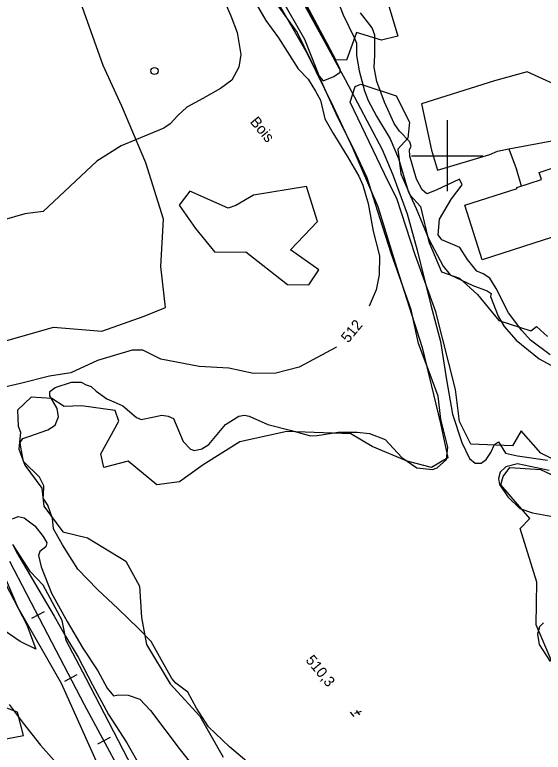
# Model space of a CAD drawing. Extents: x 347312 to 350503, y 6073086 to 6076432.
# Drawn here: x 348178.2 to 348327.1, y 6074432 to 6074639.7 of the extents above; entities that cross this region are included whole.
import ezdxf

# ---------------------------------------------------------------- set-up
doc = ezdxf.new("R2010")
doc.units = 0
for name, color, linetype in [('Level 1', 7, 'Continuous'), ('Level 19', 7, 'Continuous'), ('Level 2', 7, 'Continuous'), ('Level 21', 7, 'Continuous'), ('Level 23', 7, 'Continuous'), ('Level 3', 7, 'Continuous'), ('Level 31', 7, 'Continuous'), ('Level 36', 7, 'Continuous'), ('Level 4', 7, 'Continuous'), ('Level 44', 7, 'Continuous'), ('Level 61', 7, 'Continuous')]:
    doc.layers.add(name, color=color, linetype=linetype)

msp = doc.modelspace()

# ---------------------------------------------------------------- linework, layer by layer
at = {"layer": 'Level 1'}
msp.add_lwpolyline([(348252.29, 6074642.25), (348257.76, 6074634.67), (348263.48, 6074623), (348265.07, 6074621.13), (348268.09, 6074622.35), (348269.83, 6074623.57), (348269.9, 6074624.43), (348266.07, 6074631.8), (348259.68, 6074643.16)], dxfattribs=at)
at = {"layer": 'Level 19'}
msp.add_lwpolyline([(348317.36, 6074601.94), (348319.4, 6074596.44), (348320.88, 6074591.5)], dxfattribs=at)
at = {"layer": 'Level 2'}
for points in [[(348233.28, 6074652.95), (348239.12, 6074639.42), (348240.83, 6074634.71), (348241.92, 6074628.53), (348241.34, 6074624.96), (348239.38, 6074621.28), (348236.16, 6074618.94)], [(348241.81, 6074650.48), (348248.98, 6074638.06), (348252.5, 6074633.26), (348258.01, 6074624.53), (348260.88, 6074621.6), (348262.92, 6074618.24), (348264.31, 6074615.66), (348265.54, 6074610.4), (348267.83, 6074606.44), (348271.86, 6074599.93), (348275.16, 6074594.28), (348276.25, 6074591.72), (348277.79, 6074586.59), (348279.18, 6074578.78), (348280.94, 6074571.8), (348280.87, 6074566.51), (348280.02, 6074562.29), (348277.99, 6074557.7)], [(348268.81, 6074644.6), (348270.73, 6074639.65), (348273.83, 6074633.3), (348274.5, 6074631.72), (348274.5, 6074628.23), (348275.24, 6074623.89), (348276.74, 6074618.32), (348277.74, 6074615.55), (348280.14, 6074611.14), (348283.96, 6074604.73), (348286.33, 6074599.23), (348288.99, 6074590.08), (348291.27, 6074585.18), (348291.27, 6074585.18), (348294.87, 6074576.53), (348298.85, 6074568.88), (348300.89, 6074566.52), (348302.22, 6074565.82), (348307.26, 6074563.48), (348311.22, 6074561.97), (348312.35, 6074561.25), (348312.18, 6074560.37), (348314.34, 6074554.88), (348316.05, 6074551.9), (348319.43, 6074548.07), (348325.87, 6074542.81), (348331.28, 6074539.9)], [(348329, 6074543.95), (348323.5, 6074548.11), (348321.05, 6074550.85), (348317.26, 6074555.8), (348313.77, 6074562.61), (348312.06, 6074565.58), (348310.13, 6074566.76), (348308.39, 6074567.55), (348305.77, 6074570.78), (348303.58, 6074574.13), (348298.51, 6074576.3), (348297.44, 6074577.76), (348297.85, 6074582.16), (348301.26, 6074587.86), (348304.2, 6074591.86), (348303.46, 6074593.38), (348296.92, 6074590.33), (348294.28, 6074589.33), (348292.92, 6074590.41), (348291.35, 6074593.39), (348291.35, 6074593.39), (348289.49, 6074599.85), (348289.35, 6074601.75), (348289.85, 6074602.58), (348289.53, 6074603.91), (348286.59, 6074606.91), (348285.04, 6074609.07), (348282.35, 6074615.09), (348280.22, 6074620.92), (348279.45, 6074624.82), (348279.59, 6074628.29), (348279.61, 6074633.93), (348278.91, 6074636.02), (348275.64, 6074640.21)], [(348236.16, 6074618.94), (348231.23, 6074616.09), (348226.7, 6074613.71), (348224.13, 6074611.38), (348221.99, 6074609.02), (348220.23, 6074607.79), (348208.17, 6074602.83), (348201.31, 6074598.46), (348186.26, 6074584.29), (348181.05, 6074583.7), (348174.57, 6074581.76)], [(348217.52, 6074543.71), (348214.32, 6074545.28), (348211.27, 6074545.24), (348201.55, 6074542.34), (348194.02, 6074538.89), (348188, 6074537.93), (348179.86, 6074535.84), (348174.11, 6074534.57), (348169.66, 6074533.34), (348168.63, 6074532.33)], [(348268.88, 6074546.23), (348268.66, 6074546.02), (348258.37, 6074540.48), (348251.79, 6074538.77), (348245.42, 6074538.71), (348238.52, 6074540.23), (348230.16, 6074540.63), (348219.4, 6074542.75), (348217.52, 6074543.71)], [(348177.63, 6074497.76), (348179.21, 6074498.43), (348180.84, 6074498.08), (348183.85, 6074495.79), (348186.22, 6074492.83), (348187.23, 6074491), (348186.99, 6074489.86), (348185.29, 6074488.54), (348184.9, 6074487.41), (348185.67, 6074484.29), (348188.61, 6074476.85), (348193.04, 6074468.91), (348197.42, 6074461.35), (348201.62, 6074454.96), (348204.26, 6074450.09), (348206.05, 6074447.98), (348207.45, 6074448.23), (348210.19, 6074448.15), (348213.43, 6074447.01), (348216.43, 6074443.78), (348224.81, 6074432.76), (348232.1, 6074423.5)], [(348177.95, 6074489.93), (348178.69, 6074488.41), (348184.98, 6074477.65), (348189.31, 6074470.32), (348192.57, 6074464.78)], [(348174.35, 6074481.97), (348181.59, 6074467.9), (348184.15, 6074461.04), (348179.77, 6074463.24), (348167.05, 6074471.84)], [(348192.57, 6074464.78), (348196.11, 6074458.79), (348200.11, 6074451.05), (348204.65, 6074442.68), (348209.79, 6074434.7), (348215.8, 6074424.1)], [(348176.65, 6074445.45), (348180.64, 6074440.26), (348185.48, 6074434.06), (348197, 6074421.07)]]:
    msp.add_lwpolyline(points, dxfattribs=at)
at = {"layer": 'Level 21'}
msp.add_lwpolyline([(348355.35, 6074625.06), (348349.83, 6074623.31), (348339.45, 6074620.82), (348336.86, 6074619.53), (348331.15, 6074619.73), (348322.5, 6074623.62), (348313.34, 6074621.1), (348292.78, 6074614.64), (348295.6, 6074601.54), (348297.29, 6074595.91), (348312.03, 6074600.37), (348314.14, 6074601.34), (348317.36, 6074601.94), (348335.05, 6074605.26), (348339.96, 6074606.18), (348355.07, 6074611.84), (348359.78, 6074613.61), (348362.29, 6074614.55)], dxfattribs=at)
at = {"layer": 'Level 23'}
for p, q in [((348186.48, 6074471.61), (348182.94, 6074469.74)), ((348195.74, 6074453.88), (348192.21, 6074452.01)), ((348205.11, 6074436.21), (348201.57, 6074434.35))]:
    msp.add_line(p, q, dxfattribs=at)
msp.add_lwpolyline([(348326.4, 6074201.06), (348311.81, 6074229.17), (348300.87, 6074250.44), (348298.17, 6074255.91), (348281.64, 6074286.79), (348280.07, 6074289.79), (348271.75, 6074305.66), (348261.22, 6074325.38), (348248.86, 6074348.82), (348238.93, 6074367.57), (348229.17, 6074386.4), (348218.8, 6074405.95), (348208.19, 6074426.24), (348197.9, 6074445.44), (348186.42, 6074467.4), (348176.81, 6074485.77)], dxfattribs=at)
at = {"layer": 'Level 3'}
for p, q in [((348275.77, 6074443.53), (348273.94, 6074442.98)), ((348274.35, 6074443.84), (348275.34, 6074442.63)), ((348272.67, 6074443.36), (348273.69, 6074442.12))]:
    msp.add_line(p, q, dxfattribs=at)
at = {"layer": 'Level 31'}
msp.add_lwpolyline([(348327, 6074576.21), (348309.85, 6074570.74), (348304.96, 6074586.08), (348319.72, 6074590.79), (348319.62, 6074591.1), (348326.59, 6074593.32), (348325.95, 6074595.33), (348329.31, 6074596.4), (348330.02, 6074594.17), (348337.26, 6074596.48), (348340.37, 6074586.74), (348333.45, 6074584.53), (348335.26, 6074578.85), (348327, 6074576.21)], dxfattribs=at)
at = {"layer": 'Level 36'}
msp.add_circle((348217.59, 6074623.88), 1, dxfattribs=at)
at = {"layer": 'Level 4'}
for points in [[(348299.85, 6074514.47), (348299.85, 6074514.47), (348300.17, 6074517.97), (348298.26, 6074525.85), (348297.49, 6074532.28), (348295.25, 6074538.39), (348291.95, 6074547.16), (348289.9, 6074556.66), (348284.21, 6074572.61), (348280.47, 6074584.32), (348277.47, 6074593.79), (348273.83, 6074601.67), (348269.24, 6074610.78), (348264.55, 6074621.1), (348259.9, 6074632.73), (348253.28, 6074644.46)], [(348258.95, 6074643.98), (348265.02, 6074633), (348271.28, 6074621.52), (348281.68, 6074601.73), (348284.73, 6074594.64), (348288.78, 6074583.64), (348291.59, 6074573.42), (348295.4, 6074557.93), (348298.08, 6074547.75), (348299.84, 6074536.87), (348301.51, 6074527.28), (348304.11, 6074519.29), (348306.32, 6074514.74), (348307.93, 6074513.44), (348309.53, 6074513.42), (348310.98, 6074514.48), (348312.27, 6074516.45), (348313.3, 6074518.74)], [(348196.02, 6074483.59), (348191.68, 6074490.43), (348189.13, 6074494.93), (348188.83, 6074497.91), (348187.56, 6074501.59), (348186.27, 6074503.6), (348186.31, 6074504.54), (348186.38, 6074507.07), (348185.2, 6074509.48), (348180.72, 6074513.95), (348180.05, 6074517.37), (348179.77, 6074519.24), (348180.49, 6074520.37), (348182.23, 6074520.99), (348187.56, 6074522.8), (348189.61, 6074524.13), (348190.57, 6074526.5), (348190.17, 6074528.87), (348188.07, 6074532.39), (348188.1, 6074533.61), (348189.64, 6074534.75), (348194.2, 6074536.22), (348196.96, 6074536.25), (348198.37, 6074535.55), (348199.72, 6074535.01), (348201.16, 6074533.73), (348204.21, 6074531.53), (348206.18, 6074530.69), (348208.67, 6074529.6), (348212.52, 6074526.34), (348213.82, 6074525.77), (348217.46, 6074526.46), (348219.63, 6074526.92), (348221.42, 6074526.68), (348222.96, 6074526), (348225.7, 6074519.56), (348227.75, 6074517.36), (348228.83, 6074517.06), (348230.89, 6074517.48), (348232.85, 6074518.74), (348237.62, 6074524.29), (348241.29, 6074526.67), (348242.92, 6074526.97), (348244.29, 6074526.68), (348249.54, 6074524.35), (348255.76, 6074522.76), (348261.53, 6074521.17), (348263.42, 6074521.24), (348269.29, 6074522.14), (348274.63, 6074522.14), (348278.17, 6074521.78), (348282.54, 6074520.07), (348287.22, 6074515.09), (348291.5, 6074512.11), (348295.86, 6074511.67), (348297.21, 6074512.12), (348299.85, 6074514.47)], [(348313.3, 6074518.74), (348314.47, 6074519.41), (348316.44, 6074516.23), (348319.79, 6074515.56), (348328.22, 6074514.3)], [(348328.76, 6074511.42), (348319.81, 6074513.23), (348316.56, 6074512.41), (348314.9, 6074510.94), (348314.42, 6074509.16), (348314.73, 6074507.43), (348317.13, 6074503.93), (348320.49, 6074500.64), (348323.99, 6074499.44), (348329.21, 6074498.55)], [(348243.6, 6074429.41), (348238.68, 6074433.59), (348232.82, 6074439.17), (348229.4, 6074444.45), (348226.98, 6074448.98), (348223.56, 6074451.54), (348222.49, 6074452.83), (348219.03, 6074458.97), (348216.62, 6074463.21), (348213.05, 6074466.86), (348207.36, 6074472.43), (348201.5, 6074477.92), (348196.02, 6074483.59)], [(348327.13, 6074468.5), (348326.01, 6074467.4), (348325.46, 6074465.34), (348325.91, 6074462.35), (348329.03, 6074457.63)]]:
    msp.add_lwpolyline(points, dxfattribs=at)
at = {"layer": 'Level 44'}
for points in [[(348173.02, 6074547.17), (348189.16, 6074551.74), (348202.73, 6074550.59), (348214.66, 6074554.82), (348220.7, 6074557.29), (348219.38, 6074568.79), (348220.1, 6074582.14), (348215.16, 6074597.97), (348208.43, 6074613.95), (348203.09, 6074625.39), (348195.36, 6074647.43)], [(348281.7, 6074648.52), (348286.15, 6074633.64), (348281.47, 6074632.59), (348274.46, 6074634.7), (348271.62, 6074626.94), (348268.68, 6074627.04), (348260.47, 6074642.33)], [(348251.85, 6074644.13), (348260.56, 6074628.84), (348267.92, 6074613.88), (348273.44, 6074602.03), (348280.48, 6074585.73), (348285.7, 6074568.63), (348292.93, 6074546.06), (348298.12, 6074524.66), (348300.21, 6074514.99), (348295.6, 6074512.21), (348288.71, 6074513.99), (348278.91, 6074518.17), (348272.83, 6074521.67), (348254.83, 6074522.33), (348241.6, 6074519.44), (348231.33, 6074513), (348224.66, 6074508.2), (348218.27, 6074507.39), (348210.17, 6074514.03), (348203.28, 6074512.2), (348202.48, 6074516.05), (348207.59, 6074525.26), (348206.55, 6074528.3), (348197.07, 6074529.58), (348192.12, 6074529.37), (348188.72, 6074531.65), (348182.85, 6074532.02), (348178.99, 6074528.36), (348179.24, 6074523.91), (348179.9, 6074522.22), (348179.39, 6074517.43), (348181.1, 6074512.84), (348185.85, 6074506.43), (348186.46, 6074501.37), (348191.78, 6074494.08), (348198.69, 6074492.46), (348209.5, 6074485.82), (348213.37, 6074478.82), (348213.97, 6074469.99), (348215.33, 6074462.41), (348222.03, 6074451.3), (348230.39, 6074442.18), (348236.97, 6074430.67)], [(348335.83, 6074511.45), (348326.39, 6074516.22), (348320.8, 6074522.54), (348318.38, 6074518.36), (348306.67, 6074518.77), (348303.44, 6074525.14), (348302.35, 6074534.22), (348296.81, 6074556.05), (348291.03, 6074572.11), (348285.82, 6074587.97), (348283.34, 6074592.75), (348277.01, 6074606.12), (348272.66, 6074615.12), (348274.12, 6074619.5), (348275.66, 6074620.18), (348285.61, 6074616.89), (348289.43, 6074609.43), (348288.94, 6074604.98), (348286.12, 6074601.88), (348286.97, 6074594.92), (348289.54, 6074588.95), (348292.52, 6074585.73), (348294.81, 6074575.78), (348298.39, 6074567.34), (348303.48, 6074565.57), (348308.55, 6074560.93), (348314.53, 6074553.58), (348323.53, 6074550.7), (348325.2, 6074551.94), (348328.29, 6074549.13)], [(348234.56, 6074572.82), (348243.26, 6074573), (348255.03, 6074563.74), (348261.09, 6074563.68), (348263.86, 6074567.93), (348255.92, 6074573.49), (348263.53, 6074581.47), (348260.41, 6074591.33), (348245.45, 6074588.93), (348240.52, 6074586.03), (348238.31, 6074585.25), (348227.53, 6074590.08), (348224.55, 6074586.09), (348229.11, 6074579.54), (348234.56, 6074572.82)], [(348329.47, 6074457.62), (348325.06, 6074467.97), (348325.23, 6074479.9), (348320.56, 6074495.09), (348323.27, 6074497.83), (348315.14, 6074507.37), (348315.75, 6074509.72), (348317.61, 6074512.21), (348326.25, 6074511.66), (348335.72, 6074507.23)], [(348169.34, 6074495.52), (348178.98, 6074473.02), (348191.32, 6074451.52), (348201.55, 6074428.73)], [(348277.98, 6074301.72), (348263.08, 6074330.16), (348250.03, 6074351.98), (348234.02, 6074381.76), (348231.92, 6074390.11), (348222.59, 6074404.91), (348215.23, 6074420.26), (348198.38, 6074452.83), (348192.71, 6074463.54), (348191.56, 6074469.19), (348186.27, 6074479.11), (348182.64, 6074482.84), (348177.67, 6074490.5)], [(348171.78, 6074435.06), (348180.74, 6074436.81), (348179.05, 6074443.31), (348168.25, 6074447.34)]]:
    msp.add_lwpolyline(points, dxfattribs=at)
at = {"layer": 'Level 61'}
for p, q in [((348300, 6074610), (348300, 6074590)), ((348290, 6074600), (348310, 6074600))]:
    msp.add_line(p, q, dxfattribs=at)

# ---------------------------------------------------------------- texts
at = {"layer": 'Level 2'}
msp.add_text('512', height=3, rotation=50.5209, dxfattribs=at).set_placement((348272.13, 6074547.13))
at = {"layer": 'Level 3'}
msp.add_text('  510,3', height=3, rotation=309.5179, dxfattribs=at).set_placement((348258.57, 6074459.63))
at = {"layer": 'Level 44'}
msp.add_text('Bois', height=3, rotation=309.568, dxfattribs=at).set_placement((348244.32, 6074609.5))

doc.saveas('drawing.dxf')
